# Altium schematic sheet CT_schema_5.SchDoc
size 280 x 161 mm
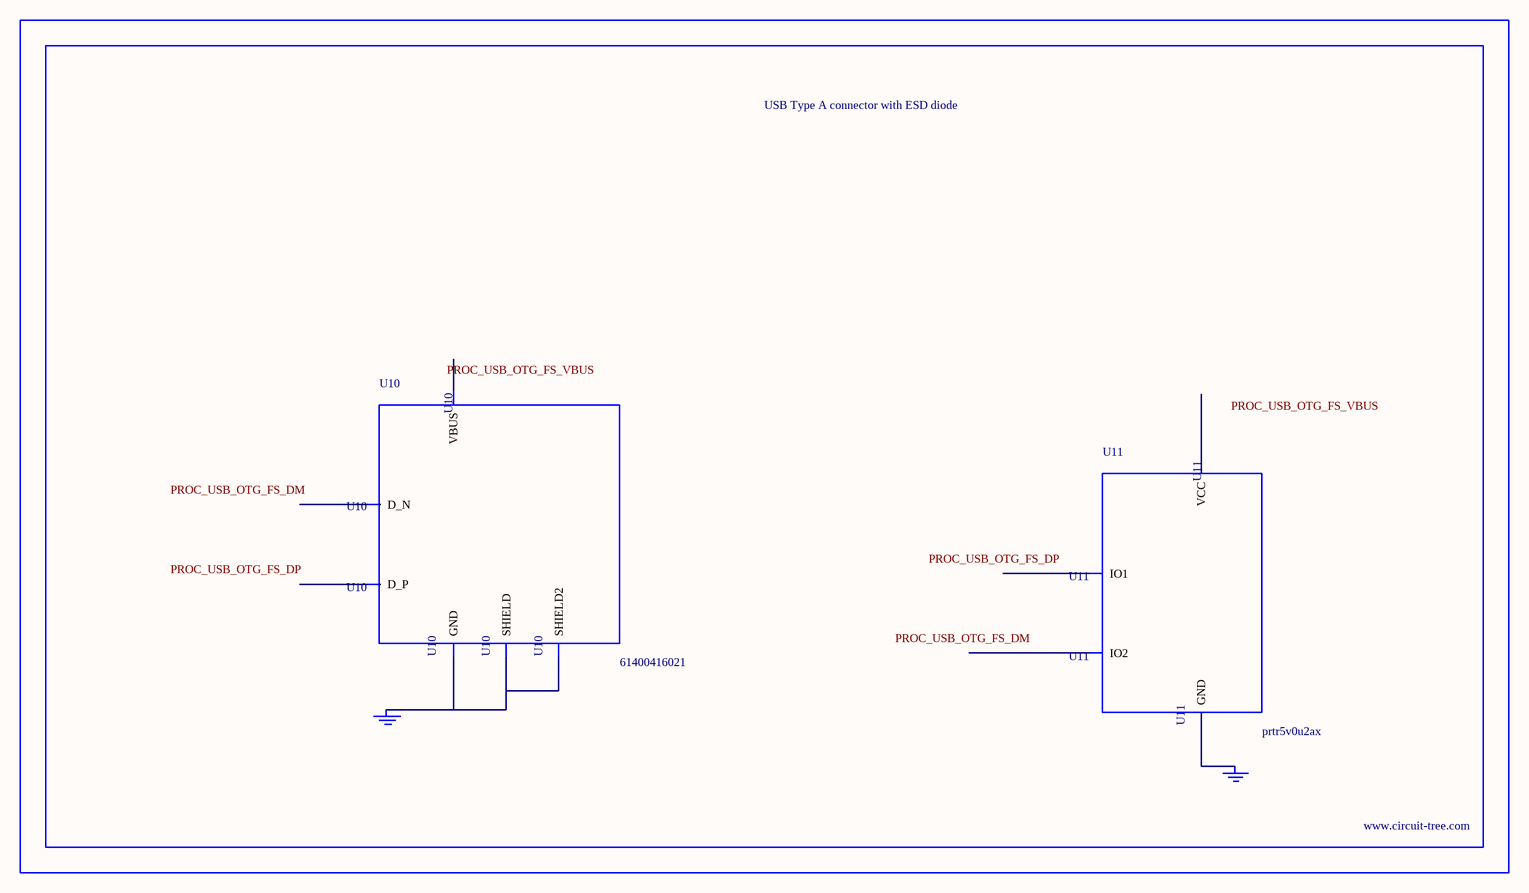
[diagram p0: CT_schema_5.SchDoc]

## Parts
BORDER4  (no value)
GND_INSTANCE_4_0  (no value)
GND_INSTANCE_4_1  (no value)
U10  61400416021  [USB-A-H]
U11  prtr5v0u2ax  [SOT143B]

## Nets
NetGND_INSTANCE_4_0_0: GND_INSTANCE_4_0.0(GND) U10.4(GND) U10.5(SHIELD) U10.6(SHIELD2)
NetGND_INSTANCE_4_1_0: GND_INSTANCE_4_1.0(GND) U11.1(GND)

Not connected (* = marked no-connect by the designer): U10 1(VBUS) 2(D_N) 3(D_P); U11 2(IO1) 3(IO2) 4(VCC)

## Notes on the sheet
- Labels drawn without touching a wire or pin: PROC_USB_OTG_FS_DM, PROC_USB_OTG_FS_DP, PROC_USB_OTG_FS_VBUS

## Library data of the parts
BORDER4 = BORDER_PAGE4
GND_INSTANCE_4_0 GND_INSTANCE_4_1 = GND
